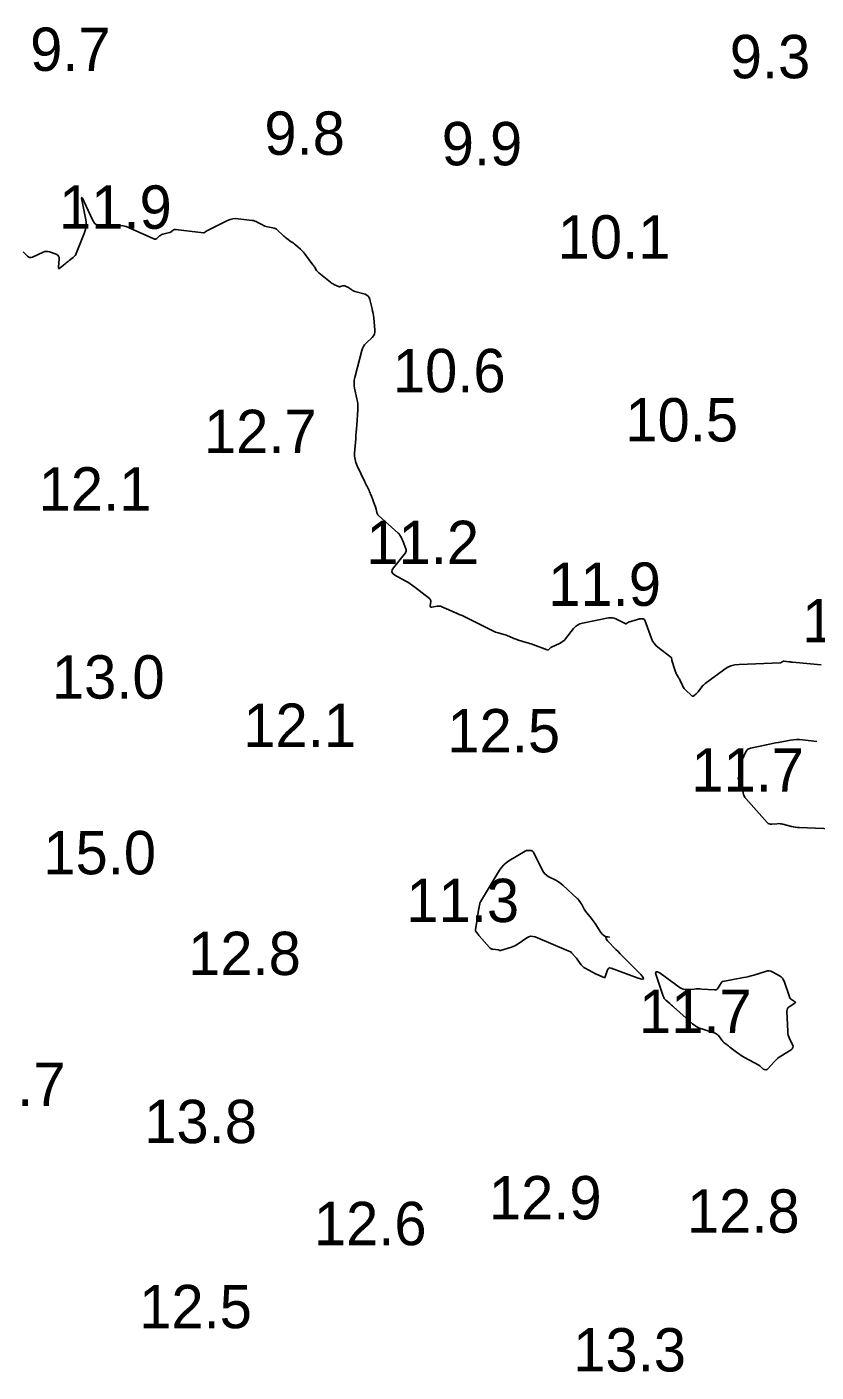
# Model space of a CAD drawing. Extents: x 815352 to 820877, y 582403 to 597439.
# Drawn here: x 819447.5 to 819538.6, y 593776.8 to 593932 of the extents above; entities that cross this region are included whole.
import ezdxf

# ---------------------------------------------------------------- set-up
doc = ezdxf.new("R2010")
doc.units = 0
doc.layers.add('V-CONT-EL12', color=7, linetype='Continuous')
doc.layers.add('V-TOPO-SOUN', color=7, linetype='Continuous')

msp = doc.modelspace()

# ---------------------------------------------------------------- linework, layer by layer
at = {"layer": 'V-CONT-EL12'}
for points in [[(819539.19, 593858.35), (819535.87, 593858.69), (819535.84, 593858.69), (819535.8, 593858.69), (819535.77, 593858.69), (819535.74, 593858.69), (819535.6, 593858.7), (819535.56, 593858.7), (819535.53, 593858.7), (819535.49, 593858.71), (819535.46, 593858.71), (819534.91, 593858.79), (819534.87, 593858.8), (819534.83, 593858.79), (819534.79, 593858.78), (819534.76, 593858.76), (819534.63, 593858.66), (819534.59, 593858.63), (819534.56, 593858.62), (819534.52, 593858.61), (819534.48, 593858.6), (819529.71, 593858.42), (819529.23, 593858.36), (819528.78, 593858.24), (819528.35, 593858.05), (819527.94, 593857.8), (819525.82, 593856.22), (819525.71, 593856.13), (819525.6, 593856.03), (819525.5, 593855.93), (819525.41, 593855.82), (819525, 593855.27), (819524.95, 593855.2), (819524.89, 593855.14), (819524.83, 593855.08), (819524.77, 593855.02), (819524.51, 593854.79), (819524.45, 593854.75), (819524.39, 593854.74), (819524.32, 593854.76), (819524.26, 593854.8), (819523.48, 593855.53), (819523.38, 593855.63), (819523.3, 593855.74), (819523.23, 593855.85), (819523.17, 593855.98), (819522.92, 593856.55), (819522.88, 593856.65), (819522.83, 593856.74), (819522.78, 593856.83), (819522.73, 593856.92), (819522.51, 593857.28), (819522.46, 593857.37), (819522.42, 593857.47), (819522.38, 593857.56), (819522.34, 593857.66), (819521.97, 593858.86), (819521.96, 593858.89), (819521.96, 593858.93), (819521.95, 593858.96), (819521.94, 593859), (819521.93, 593859.14), (819521.92, 593859.18), (819521.91, 593859.21), (819521.89, 593859.23), (819521.86, 593859.26), (819520.35, 593860.4), (819520.11, 593860.61), (819519.9, 593860.85), (819519.73, 593861.11), (819519.6, 593861.41), (819518.85, 593863.5), (819518.82, 593863.57), (819518.77, 593863.62), (819518.71, 593863.65), (819518.63, 593863.66), (819518.3, 593863.66), (819518.22, 593863.66), (819518.14, 593863.65), (819518.06, 593863.63), (819517.98, 593863.61), (819516.95, 593863.27), (819516.92, 593863.26), (819516.89, 593863.25), (819516.87, 593863.23), (819516.84, 593863.21), (819516.74, 593863.12), (819516.72, 593863.11), (819516.69, 593863.1), (819516.67, 593863.1), (819516.64, 593863.11), (819515.49, 593863.66), (819515.29, 593863.74), (819515.08, 593863.79), (819514.87, 593863.8), (819514.65, 593863.77), (819511.64, 593863.17), (819511.35, 593863.08), (819511.08, 593862.95), (819510.84, 593862.77), (819510.62, 593862.54), (819509.7, 593861.38), (819509.56, 593861.22), (819509.41, 593861.09), (819509.24, 593860.97), (819509.06, 593860.86), (819508.01, 593860.35), (819507.97, 593860.33), (819507.93, 593860.3), (819507.9, 593860.28), (819507.86, 593860.24), (819507.73, 593860.11), (819507.7, 593860.09), (819507.66, 593860.07), (819507.63, 593860.07), (819507.58, 593860.08), (819505.91, 593860.71), (819505.72, 593860.78), (819505.53, 593860.84), (819505.34, 593860.9), (819505.14, 593860.96), (819504.28, 593861.21), (819504.13, 593861.26), (819503.99, 593861.31), (819503.85, 593861.36), (819503.71, 593861.42), (819503.15, 593861.67), (819503.01, 593861.73), (819502.87, 593861.78), (819502.73, 593861.83), (819502.58, 593861.87), (819501.92, 593862.05), (819501.76, 593862.1), (819501.61, 593862.15), (819501.45, 593862.21), (819501.31, 593862.28), (819498.39, 593863.73), (819498.08, 593863.89), (819497.76, 593864.04), (819497.43, 593864.19), (819497.11, 593864.33), (819495.42, 593865.07), (819495.29, 593865.12), (819495.16, 593865.14), (819495.02, 593865.15), (819494.88, 593865.13), (819494.26, 593865.02), (819494.17, 593865.01), (819494.1, 593865.04), (819494.07, 593865.1), (819494.07, 593865.2), (819494.13, 593865.64), (819494.14, 593865.75), (819494.11, 593865.84), (819494.07, 593865.93), (819493.99, 593866), (819492.31, 593867.33), (819492.04, 593867.53), (819491.76, 593867.72), (819491.48, 593867.9), (819491.19, 593868.07), (819490, 593868.72), (819489.77, 593868.89), (819489.66, 593869.09), (819489.68, 593869.32), (819489.83, 593869.57), (819491.22, 593871.28), (819491.27, 593871.37), (819491.3, 593871.46), (819491.3, 593871.55), (819491.28, 593871.65), (819491.13, 593872.05), (819491.1, 593872.16), (819491.06, 593872.26), (819491.02, 593872.36), (819490.98, 593872.46), (819490.71, 593873.09), (819490.64, 593873.22), (819490.56, 593873.34), (819490.47, 593873.46), (819490.36, 593873.56), (819488.11, 593875.58), (819488.04, 593875.65), (819487.98, 593875.74), (819487.94, 593875.83), (819487.91, 593875.92), (819487.82, 593876.33), (819487.8, 593876.44), (819487.77, 593876.54), (819487.74, 593876.64), (819487.7, 593876.74), (819487.24, 593877.93), (819487.19, 593878.06), (819487.13, 593878.2), (819487.07, 593878.34), (819487.01, 593878.47), (819486.75, 593879.01), (819486.69, 593879.14), (819486.62, 593879.27), (819486.56, 593879.41), (819486.5, 593879.54), (819485.63, 593881.34), (819485.49, 593881.69), (819485.4, 593882.05), (819485.35, 593882.42), (819485.35, 593882.79), (819485.47, 593884.42), (819485.5, 593884.82), (819485.53, 593885.22), (819485.56, 593885.62), (819485.59, 593886.02), (819485.71, 593887.8), (819485.73, 593888.11), (819485.71, 593888.43), (819485.68, 593888.74), (819485.62, 593889.04), (819485.34, 593890.27), (819485.29, 593890.58), (819485.28, 593890.89), (819485.3, 593891.19), (819485.36, 593891.5), (819486.18, 593894.64), (819486.26, 593894.87), (819486.37, 593895.09), (819486.5, 593895.28), (819486.67, 593895.46), (819487.38, 593896.14), (819487.54, 593896.32), (819487.64, 593896.52), (819487.69, 593896.74), (819487.69, 593896.98), (819487.55, 593898.39), (819487.52, 593898.65), (819487.48, 593898.91), (819487.43, 593899.17), (819487.37, 593899.43), (819487.11, 593900.52), (819487.03, 593900.73), (819486.91, 593900.9), (819486.75, 593901.02), (819486.55, 593901.11), (819485.37, 593901.45), (819485.29, 593901.48), (819485.2, 593901.52), (819485.12, 593901.56), (819485.04, 593901.61), (819484.68, 593901.85), (819484.63, 593901.88), (819484.57, 593901.92), (819484.52, 593901.94), (819484.46, 593901.97), (819484.22, 593902.07), (819484.16, 593902.09), (819484.11, 593902.1), (819484.05, 593902.09), (819483.98, 593902.08), (819483.73, 593902), (819483.67, 593901.98), (819483.61, 593901.98), (819483.55, 593901.99), (819483.49, 593902.01), (819482.96, 593902.25), (819482.86, 593902.3), (819482.75, 593902.36), (819482.66, 593902.42), (819482.56, 593902.49), (819481.22, 593903.58), (819481.15, 593903.65), (819481.08, 593903.72), (819481.02, 593903.79), (819480.96, 593903.87), (819480.75, 593904.19), (819480.7, 593904.27), (819480.64, 593904.35), (819480.59, 593904.43), (819480.53, 593904.51), (819479.57, 593905.82), (819479.46, 593905.95), (819479.34, 593906.09), (819479.22, 593906.21), (819479.09, 593906.33), (819478.52, 593906.81), (819478.4, 593906.9), (819478.28, 593907), (819478.16, 593907.09), (819478.04, 593907.18), (819477.54, 593907.53), (819477.42, 593907.62), (819477.3, 593907.72), (819477.18, 593907.82), (819477.07, 593907.92), (819476.44, 593908.52), (819476.32, 593908.61), (819476.19, 593908.69), (819476.05, 593908.75), (819475.9, 593908.79), (819475.28, 593908.9), (819475.13, 593908.94), (819474.98, 593908.98), (819474.84, 593909.04), (819474.7, 593909.11), (819474.12, 593909.44), (819473.97, 593909.51), (819473.82, 593909.56), (819473.67, 593909.61), (819473.51, 593909.63), (819471.9, 593909.82), (819471.59, 593909.84), (819471.28, 593909.81), (819470.97, 593909.73), (819470.68, 593909.61), (819468.44, 593908.51), (819468.39, 593908.48), (819468.34, 593908.45), (819468.3, 593908.42), (819468.26, 593908.39), (819468.08, 593908.26), (819468.04, 593908.23), (819467.99, 593908.21), (819467.94, 593908.2), (819467.89, 593908.21), (819464.66, 593908.58), (819464.59, 593908.58), (819464.53, 593908.57), (819464.47, 593908.55), (819464.42, 593908.51), (819464.21, 593908.34), (819464.16, 593908.3), (819464.11, 593908.27), (819464.05, 593908.24), (819463.98, 593908.22), (819463.21, 593908.03), (819463.11, 593908), (819463.01, 593907.96), (819462.93, 593907.91), (819462.84, 593907.84), (819462.52, 593907.56), (819462.44, 593907.51), (819462.36, 593907.48), (819462.27, 593907.48), (819462.17, 593907.51), (819459.34, 593908.78), (819458.98, 593908.92), (819458.6, 593909.01), (819458.22, 593909.05), (819457.83, 593909.05), (819456.26, 593908.95), (819455.89, 593908.97), (819455.58, 593909.09), (819455.33, 593909.31), (819455.14, 593909.62), (819454.1, 593911.87), (819453.94, 593912.19), (819453.85, 593912.29), (819453.84, 593912.16), (819453.9, 593911.8), (819454.3, 593909.91), (819454.36, 593909.46), (819454.36, 593909.01), (819454.28, 593908.57), (819454.14, 593908.14), (819453.22, 593905.83), (819453.16, 593905.7), (819453.08, 593905.58), (819452.98, 593905.47), (819452.87, 593905.37), (819452.4, 593905), (819452.28, 593904.91), (819452.16, 593904.81), (819452.05, 593904.72), (819451.93, 593904.62), (819451.38, 593904.15), (819451.27, 593904.08), (819451.2, 593904.07), (819451.16, 593904.13), (819451.16, 593904.27), (819451.25, 593905.18), (819451.25, 593905.36), (819451.19, 593905.51), (819451.08, 593905.63), (819450.91, 593905.72), (819450.15, 593906), (819449.96, 593906.05), (819449.77, 593906.06), (819449.58, 593906.04), (819449.4, 593905.97), (819448.19, 593905.41), (819448.03, 593905.36), (819447.88, 593905.36), (819447.74, 593905.4), (819447.61, 593905.5), (819447.1, 593905.99)], [(819541.38, 593839.41), (819536.67, 593839.59), (819536.44, 593839.61), (819536.21, 593839.63), (819535.99, 593839.67), (819535.77, 593839.72), (819534.75, 593839.99), (819534.6, 593840.02), (819534.44, 593840.04), (819534.28, 593840.05), (819534.12, 593840.04), (819533.48, 593839.97), (819533.33, 593839.97), (819533.19, 593840.01), (819533.06, 593840.08), (819532.95, 593840.18), (819530.5, 593842.93), (819530.38, 593843.08), (819530.29, 593843.24), (819530.23, 593843.42), (819530.18, 593843.61), (819530.04, 593844.62), (819530.02, 593844.7), (819530, 593844.77), (819529.95, 593844.84), (819529.9, 593844.9), (819529.62, 593845.19), (819529.6, 593845.22), (819529.59, 593845.26), (819529.6, 593845.29), (819529.62, 593845.32), (819529.76, 593845.45), (819529.79, 593845.48), (819529.82, 593845.52), (819529.83, 593845.56), (819529.84, 593845.61), (819529.93, 593846.73), (819529.95, 593846.93), (819529.99, 593847.12), (819530.05, 593847.32), (819530.13, 593847.5), (819530.47, 593848.27), (819530.57, 593848.44), (819530.7, 593848.58), (819530.86, 593848.68), (819531.05, 593848.74), (819532.87, 593849.14), (819533.22, 593849.21), (819533.56, 593849.28), (819533.91, 593849.35), (819534.26, 593849.42), (819535.67, 593849.67), (819536.01, 593849.72), (819536.34, 593849.75), (819536.68, 593849.75), (819537.02, 593849.72), (819538.7, 593849.54)]]:
    msp.add_lwpolyline(points, dxfattribs=at)
for points in [[(819514.81, 593823.4), (819514.69, 593823.37), (819514.61, 593823.3), (819514.54, 593823.17), (819514.28, 593822.36), (819514.26, 593822.31), (819514.22, 593822.28), (819514.18, 593822.28), (819514.13, 593822.29), (819513.92, 593822.39), (819513.86, 593822.42), (819513.81, 593822.44), (819513.75, 593822.47), (819513.7, 593822.49), (819513.46, 593822.59), (819513.41, 593822.61), (819513.35, 593822.64), (819513.3, 593822.67), (819513.24, 593822.7), (819511.95, 593823.38), (819511.82, 593823.46), (819511.7, 593823.55), (819511.59, 593823.65), (819511.5, 593823.77), (819511.11, 593824.31), (819511.03, 593824.41), (819510.96, 593824.51), (819510.88, 593824.6), (819510.8, 593824.7), (819510.47, 593825.07), (819510.39, 593825.16), (819510.29, 593825.24), (819510.19, 593825.3), (819510.08, 593825.35), (819506.18, 593826.97), (819505.93, 593827.04), (819505.68, 593827.05), (819505.45, 593826.99), (819505.22, 593826.87), (819504.23, 593826.19), (819504.04, 593826.08), (819503.85, 593825.97), (819503.65, 593825.88), (819503.44, 593825.81), (819502.2, 593825.42), (819502.18, 593825.41), (819502.16, 593825.41), (819502.14, 593825.42), (819502.11, 593825.42), (819502.02, 593825.46), (819502, 593825.47), (819501.98, 593825.47), (819501.96, 593825.48), (819501.93, 593825.48), (819501.3, 593825.55), (819501.19, 593825.57), (819501.09, 593825.61), (819501, 593825.67), (819500.92, 593825.75), (819499.73, 593827.11), (819499.68, 593827.16), (819499.64, 593827.21), (819499.59, 593827.27), (819499.55, 593827.32), (819499.37, 593827.55), (819499.33, 593827.6), (819499.31, 593827.67), (819499.3, 593827.73), (819499.3, 593827.8), (819499.7, 593830.28), (819499.71, 593830.3), (819499.71, 593830.33), (819499.71, 593830.35), (819499.72, 593830.37), (819499.73, 593830.47), (819499.73, 593830.5), (819499.74, 593830.52), (819499.74, 593830.55), (819499.75, 593830.57), (819499.79, 593830.84), (819499.81, 593830.89), (819499.82, 593830.94), (819499.84, 593830.99), (819499.87, 593831.03), (819502.08, 593834.68), (819502.3, 593835), (819502.56, 593835.28), (819502.84, 593835.53), (819503.16, 593835.75), (819505.02, 593836.86), (819505.1, 593836.9), (819505.18, 593836.93), (819505.27, 593836.94), (819505.36, 593836.95), (819505.72, 593836.93), (819505.8, 593836.91), (819505.87, 593836.88), (819505.93, 593836.83), (819505.98, 593836.76), (819507.03, 593834.64), (819507.16, 593834.43), (819507.31, 593834.25), (819507.49, 593834.09), (819507.69, 593833.96), (819508.58, 593833.51), (819508.79, 593833.39), (819509, 593833.25), (819509.2, 593833.1), (819509.39, 593832.94), (819511.03, 593831.42), (819511.09, 593831.37), (819511.14, 593831.32), (819511.18, 593831.26), (819511.23, 593831.2), (819511.4, 593830.95), (819511.44, 593830.89), (819511.48, 593830.83), (819511.52, 593830.76), (819511.56, 593830.7), (819511.85, 593830.17), (819511.92, 593830.06), (819511.99, 593829.95), (819512.06, 593829.85), (819512.14, 593829.75), (819512.67, 593829.11), (819512.78, 593828.97), (819512.89, 593828.82), (819512.99, 593828.67), (819513.09, 593828.52), (819513.75, 593827.49), (819513.91, 593827.3), (819514.1, 593827.14), (819514.32, 593827.04), (819514.56, 593826.99), (819514.74, 593826.96), (819514.46, 593826.97), (819514.34, 593826.9), (819514.36, 593826.76), (819514.53, 593826.54), (819515.5, 593825.53), (819515.75, 593825.28), (819515.99, 593825.03), (819516.24, 593824.78), (819516.48, 593824.53), (819518.36, 593822.63), (819518.64, 593822.3), (819518.69, 593822.13), (819518.51, 593822.1), (819518.09, 593822.22), (819514.95, 593823.37)], [(819532.93, 593811.67), (819532.9, 593811.65), (819532.86, 593811.65), (819532.82, 593811.65), (819532.66, 593811.67), (819532.62, 593811.68), (819532.58, 593811.69), (819532.54, 593811.71), (819532.51, 593811.74), (819532.23, 593812), (819532.17, 593812.05), (819532.11, 593812.1), (819532.05, 593812.14), (819531.98, 593812.18), (819530.35, 593813.08), (819530.15, 593813.19), (819529.96, 593813.31), (819529.77, 593813.44), (819529.59, 593813.57), (819528.66, 593814.27), (819528.58, 593814.33), (819528.5, 593814.4), (819528.42, 593814.46), (819528.34, 593814.52), (819528.01, 593814.77), (819527.93, 593814.83), (819527.86, 593814.9), (819527.79, 593814.98), (819527.73, 593815.06), (819527.38, 593815.55), (819527.3, 593815.66), (819527.2, 593815.74), (819527.09, 593815.81), (819526.97, 593815.86), (819525.43, 593816.36), (819525.14, 593816.47), (819524.86, 593816.61), (819524.6, 593816.77), (819524.36, 593816.97), (819522.14, 593818.92), (819522.04, 593819.02), (819521.93, 593819.11), (819521.82, 593819.21), (819521.71, 593819.3), (819521.28, 593819.67), (819521.18, 593819.77), (819521.09, 593819.88), (819521.02, 593820), (819520.97, 593820.13), (819520.17, 593822.45), (819520.09, 593822.79), (819520.14, 593822.96), (819520.31, 593822.96), (819520.62, 593822.78), (819522.92, 593821.12), (819523.09, 593821.02), (819523.28, 593820.94), (819523.48, 593820.91), (819523.69, 593820.91), (819524.54, 593820.97), (819524.75, 593820.98), (819524.96, 593820.98), (819525.17, 593820.98), (819525.39, 593820.97), (819526.93, 593820.88), (819527.05, 593820.88), (819527.16, 593820.92), (819527.24, 593820.99), (819527.32, 593821.09), (819527.69, 593821.74), (819527.7, 593821.75), (819527.71, 593821.76), (819527.72, 593821.77), (819527.73, 593821.78), (819527.78, 593821.82), (819527.79, 593821.82), (819527.8, 593821.83), (819527.82, 593821.84), (819527.83, 593821.84), (819530.22, 593822.28), (819530.52, 593822.34), (819530.83, 593822.41), (819531.13, 593822.49), (819531.42, 593822.58), (819532.78, 593823), (819532.99, 593823.05), (819533.2, 593823.05), (819533.4, 593823.01), (819533.6, 593822.92), (819534.38, 593822.5), (819534.56, 593822.38), (819534.71, 593822.24), (819534.82, 593822.07), (819534.91, 593821.87), (819535.52, 593820.05), (819535.56, 593819.96), (819535.62, 593819.88), (819535.68, 593819.81), (819535.77, 593819.75), (819536.13, 593819.54), (819536.2, 593819.49), (819536.23, 593819.43), (819536.2, 593819.38), (819536.14, 593819.32), (819535.5, 593818.92), (819535.38, 593818.83), (819535.3, 593818.71), (819535.25, 593818.58), (819535.24, 593818.43), (819535.33, 593816.05), (819535.35, 593815.85), (819535.39, 593815.65), (819535.45, 593815.46), (819535.53, 593815.27), (819535.89, 593814.54), (819535.94, 593814.36), (819535.93, 593814.21), (819535.86, 593814.07), (819535.72, 593813.95), (819534.54, 593813.21), (819534.35, 593813.09), (819534.17, 593812.95), (819534, 593812.8), (819533.84, 593812.64), (819532.96, 593811.7)]]:
    msp.add_lwpolyline(points, close=True, dxfattribs=at)

# ---------------------------------------------------------------- texts
at = {"layer": 'V-TOPO-SOUN'}
for s, p in [('9.7', (819447.9, 593926.88)), ('9.3', (819528.64, 593926.03)), ('9.8', (819474.93, 593917.2)), ('9.9', (819495.4, 593915.99)), ('11.9 ', (819451.23, 593908.67)), ('10.1 ', (819508.78, 593905.23)), ('10.6 ', (819489.76, 593889.81)), ('10.5 ', (819516.59, 593884.13)), ('12.7 ', (819467.96, 593882.79)), ('12.1 ', (819448.88, 593876.16)), ('11.2 ', (819486.7, 593869.99)), ('11.9 ', (819507.69, 593865.17)), ('10.3 ', (819536.99, 593860.97)), ('13.0 ', (819450.41, 593854.47)), ('12.1 ', (819472.5, 593848.9)), ('12.5 ', (819496.05, 593848.27)), ('11.7 ', (819524.2, 593843.75)), ('15.0 ', (819449.42, 593834.2)), ('11.3 ', (819491.32, 593828.69)), ('12.8 ', (819466.13, 593822.58)), ('11.7 ', (819518.16, 593815.89)), ('12.7 ', (819438.96, 593807.46)), ('13.8 ', (819461.07, 593803.19)), ('12.9 ', (819500.84, 593794.4)), ('12.8 ', (819523.7, 593792.86)), ('12.6 ', (819480.64, 593791.42)), ('12.5 ', (819460.48, 593781.84)), ('13.3 ', (819510.58, 593776.85))]:
    msp.add_text(s, height=5, dxfattribs=at).set_placement(p)

doc.saveas('drawing.dxf')
